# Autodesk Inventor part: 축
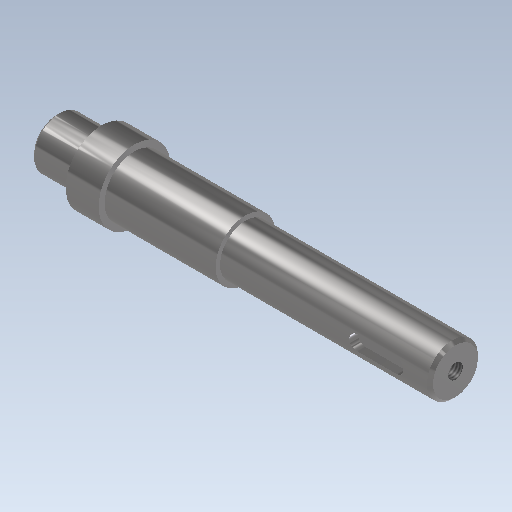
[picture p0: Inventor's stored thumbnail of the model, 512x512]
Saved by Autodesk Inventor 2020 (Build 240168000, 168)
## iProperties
Created: 2015-09
Part Number: 축
Material: 강철, 연강
Document SubType Name: Modeling
Designer: mduedu
Density: 7.86 g/cm^3
Mass: 263.424 g
Surface Area: 86.4309 cm^2
Volume: 33.5145 cm^3
Appearance: 반광택
Author: mduedu
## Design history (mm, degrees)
sketch "스케치1"
  geometry: L1 (-66.5, 0)-(66.5, 0); L2 (-66.5, 0)-(-66.5, 8.5); L3 (-66.5, 8.5)-(-51.5, 8.5); L4 (-51.5, 8.5)-(-51.5, 12); L5 (-51.5, 12)-(-40.5, 12); L6 (-40.5, 12)-(-40.5, 10); L7 (-40.5, 10)-(-3.5, 10); L8 (-3.5, 10)-(-3.5, 8.5); L9 (-3.5, 8.5)-(66.5, 8.5); L10 (66.5, 8.5)-(66.5, 0); 2 further points
  constraints: 20 end point, 5 parallel, 2 horizontal, 2 perpendicular, 1 coincident, 1 midpoint, 1 vertical
  dimensions: "d0" = 133 distance of L1.start L1.end; "d2" = 11 distance of L4.end L5.end; "d3" = 37 distance of L6.end L7.end; "d4" = 70 distance of L8.end L9.end; "d5" = 17 diameter of L3 L1; "d6" = 17 diameter of L9 L1; "d7" = 20 diameter of L7 L1; "d8" = 24 diameter of L5 L1
revolve "회전1" sketch "스케치1" stored, may be unused: angle "d9" = 90 deg
node "작업 평면1"
sketch "스케치2"
  geometry: L1 (10.5, 2.5)-(23.5, 2.5); L2 (23.5, -2.5)-(10.5, -2.5); L3 (10.5, 2.5)-(23.5, -2.5); L4 (23.5, 2.5)-(10.5, -2.5); L5 (35, -8.5)-(35, 8.5) reference; A1 r 2.5 centre (10.5, 0) between (10.5, 2.5) and (10.5, -2.5); A2 r 2.5 centre (23.5, 0) between (23.5, -2.5) and (23.5, 2.5); 2 further points
  constraints: 8 end point, 4 point on circle, 4 tangent, 2 centre point, 2 midpoint, 1 horizontal, 1 horizontal alignment, 1 parallel
  dimensions: "d10" = 18 dimension on A2 A1; "d12" = 9 distance edge to line of A2 L5; "d13" = 5 distance between parallel lines of L2 L1
extrude "돌출1" cut sketch "스케치2" distance "d14" = 3; taper "d15" = 0 deg
node "작업 평면2"
sketch "스케치4"
  geometry: L1 (9.5, -3)-(-6.5, -3); L2 (-6.5, 3)-(9.5, 3); L3 (-18.5, 10)-(-18.5, -10) reference; A1 r 3 centre (-6.5, 0) between (-6.5, 3) and (-6.5, -3); A2 r 3 centre (9.5, 0) between (9.5, -3) and (9.5, 3); 1 further point
  constraints: 4 end point, 4 point on circle, 4 tangent, 2 centre point, 1 horizontal, 1 horizontal alignment, 1 parallel
  dimensions: "d16" = 22 dimension on A1 A2; "d18" = 6 distance between parallel lines of L2 L1; "d19" = 9 distance edge to line of A1 L3
extrude "돌출2" cut sketch "스케치4" distance "d20" = 3.5; taper "d21" = 0 deg
sketch "스케치5"
  geometry: L1 (-3.5, 8.5)-(66.5, 8.5) reference; L2 (-3.5, -8.5)-(66.5, -8.5) reference; L3 (40.5, 8.5)-(40.5, -8.5); L4 (40.5, -6.5)-(38.5, -8.5); L5 (40.5, -8.5)-(38.5, -8.5); L6 (40.5, -8.5)-(40.5, -6.5); L7 (-3.5, -10)-(-3.5, 10) reference; 1 further point
  constraints: 8 end point, 4 point on line, 1 collinear, 1 perpendicular
  dimensions: "d22" = 4 diameter of L4.end L3; "d24" = 45 deg angle of L3 L4; "d26" = 44 distance between parallel lines of L3 L7
revolve "회전2" sketch "스케치5" stored, may be unused: angle "d27" = 90 deg
chamfer "모따기1" distance "d28" = 1; stored, may be unused: second distance "d29" = 2, angle "d30" = 45 deg
sketch "스케치6"
  geometry: L1 (40.5, -6.5)-(38.5, -8.5) reference; L2 (40.5, -6.5)-(42.5, -8.5) reference; 2 further points
  constraints: 1 coincident
hole "구멍1" diameter "d33" = 4.917; stored, may be unused: countersink angle "d37" = 90 deg, drill point angle "d39" = 118 deg; dims "d34" = 12, "d35" = 4, "d36" = 2, "d38" = 15, "d42" = 10, "d43" = 10
node "솔리드1"
